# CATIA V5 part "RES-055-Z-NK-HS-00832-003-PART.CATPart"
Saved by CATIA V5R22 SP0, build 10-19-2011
Part number: DISTANZPLATTE_003
Revision: 1
Definition: RES-055-Z-NK-HS-00832-003-PART
Nomenclature: RES-055-Z-NK-HS-00832-003-PART
Property "Pos.:": "003"
Property "Benennung:": "DISTANZPLATTE"
Property "Kom_Nr.:": "15030"
Property "Werkstoff": "1.2343"
Property "Warmbehandlung": "gasnitriert, 38-40HRc EHT 0,012"
Property "Drahtschnitt": "-"
Property "Rundes_Teil": "-"
Property "Fm_laenge": "N.A"
Property "Fm_breite": "N.A"
Property "Fm_hoehe": "N.A"
Property "Rm_laenge": "N.A"
Property "Rm_breite": "N.A"
Property "Rm_hoehe": "N.A"
Property "Fertiggewicht": 0 (mass)
Property "Rohteilgewicht": 0 (mass)
Property "Teiletyp": "--"
Property "DichteMaterial": 0 (density)
Bounding box of the stored display mesh (mm): x -526 to 650, y -400 to 418, z 98 to 158
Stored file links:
  C:\Users\gerco\Desktop\Heck a Becker\HS-832_6_11_2017\OBERTEIL\RES-055-Z-NK-HS-00832-003-PART.CATPart
  X:\Projekte\Ford\045-Z-NK-HS-00270\Stammdaten__\Gueltige-Daten\DGF\AS\Einsatz_AS\RES-045-Z-NK-HS-00270-0085-PRODUCT.CATProduct
  C:\Users\gerco\Desktop\Heck a Becker\HS-832_6_11_2017\RES-055-Z-NK-HS-00832-0001-MP.CATProduct
  C:\Users\gerco\Desktop\Heck a Becker\HS-832_6_11_2017\OBERTEIL\RES-055-Z-NK-HS-00832-002-PART.CATPart
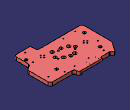
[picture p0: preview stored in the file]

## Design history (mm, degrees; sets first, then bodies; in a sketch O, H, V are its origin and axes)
External parameters (linked from other documents)
  `External.Part-Aktualisiert` = "Nein"
AxisSystem1 "Zeichnung": origin (-88.3577, -2.1174, 100), X (1, 0, 0), Y (0, 1, 0), Z (0, 0, 1)
Set1
  Point1: type Center, Curve DatumCurve1
  DatumCurve1
  Point2: type Center, Curve DatumCurve2
  DatumCurve2
  Sketch1 on start face of Pad1, origin (0, 0, 98), H (1, 0, 0), V (0, -1, 0)
    line L1 (-323.4192, -216.5405) -> (-223.2604, -148.9825)
    reference intersected line E1 through (-172.4335, -116.3079) direction (0.5592, -0.829) from face of DatumSurface1
    perpendicularity: E1 L1
  DatumSurface1
  Sketch2 on start face of Pad1, origin (0, 0, 98), H (1, 0, 0), V (0, -1, 0)
    line L1 (-288.8097, 97.9157) -> (-364.2918, 74.8385)
    reference projected line E1 (-162.6193, 115.1729) -> (-138.8677, 122.4345) from edge of DatumCurve3
    parallelism: L1 E1
  DatumCurve3
  Extract1: ExtractElem face of DatumSurface2
  DatumSurface2
  DatumCurve4
  DatumCurve5
  DatumPoint1
  Sketch3, origin (13, -18, 158), H (1, 0, 0), V (0, 1, 0)
    point P1 (251.3624, -208.4253)
    point P2 (472.1176, -115.8126)
    point P3 (556.6916, 242.4095)
    point P4 (336.7469, 310.6472)
    point P5 (162.6938, 310.4125)
    point P6 (-82.7818, 310.5732)
    point P7 (-333.9619, 325.7225)
    point P8 (-155.8091, -208.4253)
    point P9 (-369.5402, -211.2042)
    point P10 (395.0817, -331.375)
  DatumCurve6
  Sketch4, origin (13, -18, 198), H (1, 0, 0), V (0, -1, 0), geometry linked from another document
  DatumPoint2
  Sketch5, origin (0, 0, 58), H (1, 0, 0), V (0, -1, 0), geometry linked from another document
  DatumPoint3
  Sketch6, origin (0, 0, 58), H (1, 0, 0), V (0, -1, 0), geometry linked from another document
  DatumCurve7 to DatumCurve11
  Sketch7, origin (0, 0, 58), H (1, 0, 0), V (0, -1, 0), geometry linked from another document
  DatumCurve12
  DatumCurve13
  DatumPoint4
  Sketch8, origin (0, 0, 20), H (1, 0, 0), V (0, -1, 0), geometry linked from another document
  DatumCurve14
  DatumCurve15
  Sketch9 on end face of Pad1, origin (0, 0, 158), H (1, 0, 0), V (0, 1, 0)
    point P1 (310, -110)
    point P2 (340, -140)
    point P3 (310, -170)
    point P4 (280, -140)
    reference projected circle E1 centre (280, -140) radius 2.4585 from edge of DatumCurve16
    reference projected circle E2 centre (310, -170) radius 2.4585 from edge of DatumCurve17
    reference projected circle E3 centre (340, -140) radius 2.4585 from edge of DatumCurve18
    reference projected circle E4 centre (310, -110) radius 2.4585 from edge of DatumCurve19
    point P5 (-290.0001, 49.9999)
    point P6 (-260.0001, 19.9999)
    point P7 (-290.0001, -10.0001)
    point P8 (-320.0001, 19.9999)
    reference projected circle E5 centre (-320.0001, 19.9999) radius 2.4585 from edge of DatumCurve20
    reference projected circle E6 centre (-290.0001, 49.9999) radius 5.5 from edge of DatumCurve21
    reference projected circle E7 centre (-260.0001, 19.9999) radius 5.5 from edge of DatumCurve22
    reference projected point E8 (-290.0001, -10.0001) from vertex of DatumPoint5
    concentricity: P4 E1, P3 E2, P2 E3, P1 E4, P8 E5, P5 E6, P6 E7
    coincidence: P7 E8
  DatumCurve16 to DatumCurve22
  DatumPoint5
  Sketch10 on start face of Pad1, origin (0, 0, 98), H (1, 0, 0), V (0, -1, 0)
    point P1 (241.3317, -171.4183)
    point P2 (296.3157, -170.0917)
    point P3 (297.5217, -220.0772)
    point P4 (242.5377, -221.4037)
    reference projected circle E1 centre (241.3317, -171.4183) radius 6.5 from edge of DatumCurve23
    reference projected circle E2 centre (296.3157, -170.0917) radius 6.5 from edge of DatumCurve24
    reference projected circle E3 centre (242.5377, -221.4037) radius 6.5 from edge of DatumCurve25
    reference projected circle E4 centre (297.5217, -220.0772) radius 6.5 from edge of DatumCurve26
    point P5 (303.7518, -318)
    point P6 (504.7518, -318)
    reference projected line E5 (297.2518, -298.6917) -> (297.2518, -333.6917) from edge of DatumCurve29
    reference projected line E6 (498.2518, -298.6917) -> (498.2518, -333.6917) from edge of DatumCurve30
    reference projected line E7 (650, -338) -> (229.3301, -338) from edge [start face of Pad1 | face of Pad1 from Sketch18.L11]
    reference projected line E8 (650, -338) -> (229.3301, -338) from edge [start face of Pad1 | face of Pad1 from Sketch18.L11]
    point P7 (537.8948, 114.8277)
    point P8 (587.104, 80.499)
    point P9 (505.8547, 68.8992)
    point P10 (555.0638, 34.5705)
    reference projected circle E9 centre (587.104, 80.499) radius 6.5 from edge of DatumCurve51
    reference projected circle E10 centre (537.8948, 114.8277) radius 6.5 from edge of DatumCurve52
    reference projected circle E11 centre (555.0638, 34.5705) radius 6.5 from edge of DatumCurve53
    reference projected circle E12 centre (505.8547, 68.8992) radius 6.5 from edge of DatumCurve54
    distance P5 E5 = 6.5
    distance P6 E6 = 6.5
    distance E7 P6 = 20
    distance E8 P5 = 20
    concentricity: P1 E1, P2 E2, P4 E3, P3 E4, P8 E9, P7 E10, P10 E11, P9 E12
  DatumCurve23 to DatumCurve30
  Sketch11 on start face of Pad1, origin (0, 0, 98), H (1, 0, 0), V (0, -1, 0)
    point P1 (-294.3836, -261.3208)
    point P2 (-264.7464, -305.2598)
    point P3 (-397.3924, -394.7307)
    point P4 (-427.0296, -350.7917)
    reference projected circle E1 centre (-427.0296, -350.7917) radius 11.4 from edge of DatumCurve31
    reference projected circle E2 centre (-397.3924, -394.7307) radius 11.4 from edge of DatumCurve32
    reference projected circle E3 centre (-294.3836, -261.3208) radius 11.4 from edge of DatumCurve33
    reference projected circle E4 centre (-264.7464, -305.2598) radius 11.4 from edge of DatumCurve34
    point P5 (-303.3006, 105.6705)
    point P6 (-287.8049, 54.9864)
    point P7 (-456.3094, 58.891)
    point P8 (-440.8137, 8.2069)
    reference projected circle E5 centre (-456.3094, 58.891) radius 11.4 from edge of DatumCurve35
    reference projected circle E6 centre (-440.8137, 8.2069) radius 11.4 from edge of DatumCurve36
    reference projected circle E7 centre (-303.3006, 105.6705) radius 11.4 from edge of DatumCurve37
    reference projected circle E8 centre (-287.8049, 54.9864) radius 11.4 from edge of DatumCurve38
    point P9 (315, 386.5)
    point P10 (315, 333.5)
    point P11 (475, 386.5)
    point P12 (475, 333.5)
    reference projected circle E9 centre (315, 386.5) radius 11.4 from edge of DatumCurve39
    reference projected circle E10 centre (315, 333.5) radius 11.4 from edge of DatumCurve40
    reference projected circle E11 centre (475, 386.5) radius 11.4 from edge of DatumCurve41
    reference projected circle E12 centre (475, 333.5) radius 11.4 from edge of DatumCurve42
    concentricity: P4 E1, E2 P3, P1 E3, P2 E4, P7 E5, P8 E6, P5 E7, P6 E8, P9 E9, P10 E10, P11 E11, P12 E12
  DatumCurve31 to DatumCurve46
  Sketch12 on end face of Pocket1, origin (0, 0, 118), H (1, 0, 0), V (0, -1, 0)
    point P1 (7.4997, -339.4905)
    point P2 (5.65, -392.4582)
    point P3 (-154.2525, -386.8743)
    point P4 (-152.4028, -333.9066)
    reference projected circle E1 centre (-152.4028, -333.9066) radius 11.4 from edge of DatumCurve47
    reference projected circle E2 centre (-154.2525, -386.8743) radius 11.4 from edge of DatumCurve48
    reference projected circle E3 centre (7.4997, -339.4905) radius 11.4 from edge of DatumCurve49
    reference projected circle E4 centre (5.65, -392.4582) radius 11.4 from edge of DatumCurve50
    concentricity: P4 E1, E2 P3, P1 E3, P2 E4
  DatumCurve47 to DatumCurve54
  Sketch13 on start face of Pad1, origin (0, 0, 98), H (1, 0, 0), V (0, -1, 0)
    point P1 (-279.565, -283.2903)
    point P2 (-412.211, -372.7612)
    reference projected circle E1 centre (-412.211, -372.7612) radius 5.5 from edge of DatumCurve55
    reference projected circle E2 centre (-279.565, -283.2903) radius 5.5 from edge of DatumCurve56
    point P3 (-295.5528, 80.3284)
    point P4 (-448.5616, 33.549)
    reference projected circle E3 centre (-448.5616, 33.549) radius 5.5 from edge of DatumCurve57
    reference projected circle E4 centre (-295.5528, 80.3284) radius 5.5 from edge of DatumCurve58
    point P5 (475, 360)
    point P6 (315, 360)
    reference projected circle E5 centre (315, 360) radius 5.5 from edge of DatumCurve59
    reference projected circle E6 centre (475, 360) radius 5.5 from edge of DatumCurve60
    point P7 (562.4994, 97.6633)
    point P8 (530.4592, 51.7348)
    reference projected circle E7 centre (530.4592, 51.7348) radius 5.5 from edge of DatumCurve61
    reference projected circle E8 centre (562.4994, 97.6633) radius 5.5 from edge of DatumCurve62
    point P9 (276.3216, -170.5741)
    point P10 (262.5319, -220.9213)
    reference projected circle E9 centre (276.3216, -170.5741) radius 5 from edge of DatumCurve96
    reference projected circle E10 centre (262.5319, -220.9213) radius 5 from edge of DatumCurve97
    concentricity: P2 E1, P1 E2, E3 P4, P3 E4, P6 E5, P5 E6, P8 E7, P7 E8, P9 E9, P10 E10
  DatumCurve55 to DatumCurve62
  Sketch14 on start face of Pad1, origin (0, 0, 98), H (1, 0, 0), V (0, -1, 0)
    point P1 (-402.6103, -199.2242)
    point P2 (-430.5699, -157.7723)
    point P3 (-513.4737, -213.6916)
    point P4 (-485.5141, -255.1435)
    reference projected circle E1 centre (-485.5141, -255.1435) radius 4.4 from edge of DatumCurve63
    reference projected circle E2 centre (-513.4737, -213.6916) radius 4.4 from edge of DatumCurve64
    reference projected circle E3 centre (-402.6103, -199.2242) radius 4.4 from edge of DatumCurve65
    reference projected circle E4 centre (-430.5699, -157.7723) radius 4.4 from edge of DatumCurve66
    point P5 (-403.2616, 244.5115)
    point P6 (-498.8921, 215.2743)
    point P7 (-484.2735, 167.459)
    point P8 (-388.643, 196.6962)
    reference projected circle E5 centre (-388.643, 196.6962) radius 4.4 from edge of DatumCurve67
    reference projected circle E6 centre (-403.2616, 244.5115) radius 4.4 from edge of DatumCurve68
    reference projected circle E7 centre (-498.8921, 215.2743) radius 5.5 from edge of DatumCurve69
    reference projected circle E8 centre (-484.2735, 167.459) radius 4.4 from edge of DatumCurve70
    point P9 (470, 221.5)
    point P10 (370, 221.5)
    point P11 (370, 171.5)
    point P12 (470, 171.5)
    reference projected circle E9 centre (370, 221.5) radius 4.4 from edge of DatumCurve71
    reference projected circle E10 centre (470, 221.5) radius 5.5 from edge of DatumCurve72
    reference projected arc E11 centre (470, 171.5) radius 2.86 from (472.453, 172.9705) to (470.047, 174.3596) ccw from edge of DatumCurve73
    reference projected circle E12 centre (370, 171.5) radius 5.5 from edge of DatumCurve74
    point P13 (556.1354, -46.0403)
    point P14 (527.5281, -87.0479)
    point P15 (609.5433, -144.2625)
    point P16 (638.1506, -103.2549)
    reference projected circle E13 centre (638.1506, -103.2549) radius 5.5 from edge of DatumCurve75
    reference projected circle E14 centre (609.5433, -144.2625) radius 5.5 from edge of DatumCurve76
    reference projected circle E15 centre (556.1354, -46.0403) radius 5.5 from edge of DatumCurve77
    reference projected circle E16 centre (527.5281, -87.0479) radius 5.5 from edge of DatumCurve78
    concentricity: P4 E1, P3 E2, P1 E3, P2 E4, E5 P8, P5 E6, P6 E7, P7 E8, P10 E9, P9 E10, P12 E11, P11 E12, P16 E13, P15 E14, P13 E15, P14 E16
  DatumCurve63 to DatumCurve82
  Sketch15 on start face of Pad1, origin (0, 0, 98), H (1, 0, 0), V (0, -1, 0)
    point P1 (-493.3428, -243.537)
    point P2 (-410.439, -187.6177)
    reference projected circle E1 centre (-493.3428, -243.537) radius 3 from edge of DatumCurve83
    reference projected circle E2 centre (-410.439, -187.6177) radius 2.7856 from edge of DatumCurve84
    point P3 (-392.7363, 210.0845)
    point P4 (-488.3667, 180.8473)
    reference projected circle E3 centre (-488.3667, 180.8473) radius 3 from edge of DatumCurve85
    reference projected circle E4 centre (-392.7363, 210.0845) radius 1.65 from edge of DatumCurve86
    point P5 (470, 207.5)
    point P6 (370, 207.5)
    reference projected circle E5 centre (370, 207.5) radius 3 from edge of DatumCurve87
    reference projected circle E6 centre (470, 207.5) radius 2.7856 from edge of DatumCurve88
    point P7 (630.1405, -114.7371)
    point P8 (548.1253, -57.5225)
    reference projected circle E7 centre (548.1253, -57.5225) radius 3 from edge of DatumCurve89
    reference projected circle E8 centre (630.1405, -114.7371) radius 3 from edge of DatumCurve90
    concentricity: E1 P1, P2 E2, P4 E3, P3 E4, P6 E5, P5 E6, P8 E7, E8 P7
  DatumCurve83 to DatumCurve90
  Sketch16 on end face of Pocket1, origin (0, 0, 118), H (1, 0, 0), V (0, -1, 0)
    point P1 (47.4404, -341.8859)
    point P2 (147.3795, -345.3759)
    reference projected circle E1 centre (47.4404, -341.8859) radius 3 from edge of DatumCurve91
    reference projected circle E2 centre (147.3795, -345.3759) radius 3 from edge of DatumCurve92
    concentricity: P1 E1, P2 E2
  DatumCurve91 to DatumCurve93
  DatumSurface3
  DatumCurve94
  DatumSurface4
  DatumCurve95
  DatumSurface5
  DatumCurve96
  DatumCurve97
Set2 "Berechnen"
  Plane1 "Pos-XY": type Offset, RefPlane xy-plane, Offset 0
  Plane2 "Pos-YZ": type Offset, RefPlane yz-plane, Offset 0
  Plane3 "Pos-ZX": type Offset, RefPlane zx-plane, Offset 0
  UdfFeature1 "Fertigmass.A": UdfInputSpec1 Extremum1, UdfInputSpec2 edge [XY plane of AxisSystem1 | ZX plane of AxisSystem1], UdfInputSpec3 edge [YZ plane of AxisSystem1 | XY plane of AxisSystem1], UdfInputSpec4 edge [ZX plane of AxisSystem1 | YZ plane of AxisSystem1], UdfInputSpec5 Extremum2, UdfInputSpec6 edge [XY plane of AxisSystem1 | ZX plane of AxisSystem1], Abmessungen "16mm x 16mm x 615,406mm", X 16, Y 16, Z 615.406, UdfInputSpec7 edge [YZ plane of AxisSystem1 | XY plane of AxisSystem1], UdfInputSpec8 edge [ZX plane of AxisSystem1 | YZ plane of AxisSystem1], UdfInputSpec9 Extremum3, UdfInputSpec10 edge [YZ plane of AxisSystem1 | XY plane of AxisSystem1], UdfInputSpec11 edge [XY plane of AxisSystem1 | ZX plane of AxisSystem1], UdfActivity false, UdfInputSpec12 edge [ZX plane of AxisSystem1 | YZ plane of AxisSystem1], UdfInputSpec13 Extremum4, UdfInputSpec14 edge [YZ plane of AxisSystem1 | XY plane of AxisSystem1], UdfInputSpec15 edge [XY plane of AxisSystem1 | ZX plane of AxisSystem1], UdfInputSpec16 edge [ZX plane of AxisSystem1 | YZ plane of AxisSystem1], UdfInputSpec17 Extremum5, UdfInputSpec18 edge [ZX plane of AxisSystem1 | YZ plane of AxisSystem1], UdfInputSpec19 edge [XY plane of AxisSystem1 | ZX plane of AxisSystem1], UdfInputSpec20 edge [YZ plane of AxisSystem1 | XY plane of AxisSystem1], UdfOutputs Trim3, UdfInputSpec21 Extremum6, UdfInputSpec22 edge [ZX plane of AxisSystem1 | YZ plane of AxisSystem1], UdfActivityImpacts (edge [XY plane of AxisSystem1 | ZX plane of AxisSystem1]; edge [YZ plane of AxisSystem1 | XY plane of AxisSystem1]; Plane6; Plane7; Plane8; Plane9; Plane10; Plane11; Intersect1; Intersect2; Intersect3; Intersect4; Intersect5; Intersect6; Intersect7; Intersect8; Intersect9; Intersect10; Intersect11; Intersect12; Trim1; Trim2; Trim4; Trim5; Trim6; Split1; Split2; Split3; Split4; Point3; Plane12; Plane13; Plane14; Plane15; Plane16; Plane17), UdfInputSpec25 {planeoffsetpt RefPlane YZ plane of AxisSystem1, RefPoint Extremum1}, UdfInputSpec26 {planeoffsetpt RefPlane YZ plane of AxisSystem1, RefPoint Extremum2}, UdfInputSpec27 {planeoffsetpt RefPlane ZX plane of AxisSystem1, RefPoint Extremum3}, UdfInputSpec28 {planeoffsetpt RefPlane ZX plane of AxisSystem1, RefPoint Extremum4}, UdfInputSpec29 {planeoffsetpt RefPlane XY plane of AxisSystem1, RefPoint Extremum5}, UdfInputSpec30 {planeoffsetpt RefPlane XY plane of AxisSystem1, RefPoint Extremum6}
  DatumSurface6
  Plane4 "Pos-YZ": stored without definition
  Plane5 "Pos-ZX": stored without definition
  Sketch17 on end face of Pocket1, origin (0, 0, 118), H (1, 0, 0), V (0, -1, 0)
    point P1 (6.5749, -365.9744)
    point P2 (-153.3277, -360.3905)
    reference projected circle E1 centre (-153.3277, -360.3905) radius 5.5 from edge of DatumCurve98
    reference projected circle E2 centre (6.5749, -365.9744) radius 5.5 from edge of DatumCurve99
    concentricity: P2 E1, P1 E2
  DatumCurve98
  DatumCurve99
Body1 (main body)
  Body2 "Grundkörper"
    Body3
      Sketch18 on face of DatumSurface6, origin (0, 0, 98), H (1, 0, 0), V (0, 1, 0)
        line L1 (-411, 418) -> (-404.0042, 418)
        line L2 (550, -400) -> (264, -400)
        line L3 (-526, -280) -> (-526, 247.5055)
        point P1 (550, 400)
        reference intersected line E1 through (0, 0) direction (0, 1) from Plane4
        reference intersected line E2 through (0, 0) direction (-1, 0) from Plane5
        line L4 (550, -128.4331) -> (650, -58.6722)
        reference projected line E3 (622.675, -70.3157) -> (536.5591, -130.391) from edge of DatumCurve4
        line L5 (550, -128.4331) -> (550, -400)
        point P4 (550, 230)
        reference intersected line E4 through (0, 0) direction (-1, 0) from zx-plane
        line L6 (-411, 418) -> (-526, 247.5055)
        point P6 (-411, 418)
        reference projected line E5 (-406.4241, 417.1065) -> (-451.1595, 350.7835) from edge of DatumCurve5
        line L7 (650, 338) -> (650, -58.6722)
        line L8 (264, -400) -> (264, -280)
        point P10 (264, -280)
        line L9 (264, -280) -> (-526, -280)
        point P11 (-336, -280)
        line L10 (229.3301, 418) -> (229.3301, 338)
        line L11 (229.3301, 338) -> (650, 338)
        line L12 (-346, 383) -> (-206, 383)
        line L13 (-186, 403) -> (-186, 418)
        line L14 (-186, 418) -> (229.3301, 418)
        arc A1 centre (-346, 403) radius 20 from (-346, 383) to (-357.1839, 386.4192) cw
        arc A2 centre (-206, 403) radius 20 from (-206, 383) to (-186, 403) ccw
        line L15 (-357.1839, 386.4192) -> (-404.0042, 418)
        distance E1 L3 = 526
        distance E2 L1 = 418
        distance P4 L2 = 630
        distance E4 L2 = 400
        distance L3 P6 = 115
        distance L5 L7 = 100
        distance L5 L3 = 1076
        distance L9 L2 = 120
        distance P10 P11 = 600
        distance L1 L11 = 80
        distance L12 L1 = 35
        radius A1 = 20
        radius A2 = 20
        horizontal: L1 H, L2 H, L9 H, L11 H, L12 H
        vertical: L3 V, L7 V, L8 V, L10 V, L13 V
        parallelism: E3 L4, L6 E5
        coincidence: P6 L1, P11 L9, L1 L14
        tangency: A1 L12, A2 L12, A2 L13, L15 A1
        perpendicularity: L15 L6
      Pad1: profile Sketch18, direction (0, 0, 1), length 60
    Assemble1: tool Body3
    Fillet1: radius 40, on edge [face of Pad1 from Sketch18.L5 | face of Pad1 from Sketch18.L2]; edge [face of Pad1 from Sketch18.L4 | face of Pad1 from Sketch18.L5] (x2); edge [face of Pad1 from Sketch18.L3 | face of Pad1 from Sketch18.L6]; edge [face of Pad1 from Sketch18.L7 | face of Pad1 from Sketch18.L4]; edge [face of Pad1 from Sketch18.L8 | face of Pad1 from Sketch18.L9]; edge [face of Pad1 from Sketch18.L9 | face of Pad1 from Sketch18.L3]; edge [face of Pad1 from Sketch18.L11 | face of Pad1 from Sketch18.L7]; edge [face of Pad1 from Sketch18.L10 | face of Pad1 from Sketch18.L11]; edge [face of Pad1 from Sketch18.L14 | face of Pad1 from Sketch18.L10]
  Assemble2 "Grundkörper": tool Body2
  Body4 "Fräsbearbeitung"
    Body5
      Sketch19 on start face of Pad1, origin (0, 0, 98), H (1, 0, 0), V (0, -1, 0)
        line L1 (-191, -427.6592) -> (161, -427.6592)
        line L2 (161, -427.6592) -> (161, -327)
        line L3 (150, -316) -> (-180, -316)
        line L4 (-191, -327) -> (-191, -427.6592)
        point P3 (161, -316)
        point P4 (-191, -316)
        reference projected line E1 (-526, -247.5055) -> (-526, 280) from edge [start face of Pad1 | face of Pad1 from Sketch18.L3]
        arc A1 centre (-180, -327) radius 11 from (-191, -327) to (-180, -316) cw
        arc A2 centre (150, -327) radius 11 from (150, -316) to (161, -327) cw
        reference projected line E2 (-404.0042, -418) -> (-411, -418) from edge [start face of Pad1 | face of Pad1 from Sketch18.L1]
        distance L4 E1 = 335
        distance P3 P4 = 352
        radius A1 = 11
        radius A2 = 11
        distance L3 E2 = 102
        horizontal: L1 H, L3 H
        vertical: L2 V, L4 V
        coincidence: L4 P4, L3 P4, L3 P3, L2 P3
        tangency: A1 L4, A1 L3, A2 L3, A2 L2
      Pocket1: profile Sketch19, direction (0, 0, 1), length 20
    Assemble3: tool Body5
    Body6
      Sketch20 on end face of Pad1, origin (-420, -131, 158), H (1, 0, 0), V (0, 1, 0)
        point P1 (0, 0)
        reference projected point E1 (0, 0) from vertex of Sketch4
        coincidence: E1 P1
      Hole1: placed by Sketch20, at (-420, -131, 158) direction (0, 0, -1), diameter 50, depth 5
      UserPattern1: of the body so far, copies 4, at the points of Sketch4
    Assemble4: tool Body6
    Body7
      Sketch21 on start face of Pad1, origin (-130, 0, 98), H (1, 0, 0), V (0, -1, 0)
        point P1 (0, 0)
        reference projected point E1 (0, 0) from vertex of DatumPoint2
        coincidence: E1 P1
      Hole2: placed by Sketch21, at (-130, 0, 98) direction (0, 0, 1), diameter 55, depth 70
      UserPattern2: of the body so far, copies 4, at the points of Sketch5
    Assemble5: tool Body7
    Body8
      Sketch22 on start face of Pad1, origin (-75, -63, 98), H (1, 0, 0), V (0, -1, 0)
        point P1 (0, 0)
        reference projected point E1 (0, 0) from vertex of DatumPoint3
        coincidence: E1 P1
      Hole3: placed by Sketch22, at (-75, -63, 98) direction (0, 0, 1), diameter 62, depth 70
      UserPattern3: of the body so far, copies 4, at the points of Sketch7
    Assemble6: tool Body8
    Body9
      Sketch23 on start face of Pad1, origin (391.3896, -114.9501, 98), H (1, 0, 0), V (0, -1, 0)
        point P1 (-81.3896, 25.0499)
        reference projected line E1 (258.6104, -56.2779) -> (258.6104, -452.9501) from edge [start face of Pad1 | face of Pad1 from Sketch18.L7]
        distance P1 E1 = 340
      Hole4: placed by Sketch23, at (310, -140, 98) direction (0, 0, 1), diameter 72, depth 5
      Sketch24 on start face of Pad1, origin (-260.8683, 132.2894, 98), H (1, 0, 0), V (0, -1, 0)
        point P1 (-29.1318, 112.2895)
        reference projected circle E1 centre (-29.1318, 112.2895) radius 36.5 from edge of DatumCurve13
        concentricity: E1 P1
      Hole5: placed by Sketch24, at (-290.0001, 19.9999, 98) direction (0, 0, 1), diameter 72, depth 5
    Assemble7: tool Body9
  Assemble8 "Fräsbearbeitung": tool Body4
  Body10 "Bohrbearbeitung"
    Body11
      Sketch25 on start face of Pad1, origin (-142.8091, -226.4253, 98), H (1, 0, 0), V (0, -1, 0)
        point P1 (0, 0)
        reference projected point E1 (0, 0) from vertex of DatumPoint1
        coincidence: E1 P1
      Hole6: placed by Sketch25, at (-142.8091, -226.4253, 98) direction (0, 0, 1), diameter 17.5, depth 70, V-bottom angle 120, counterbore diameter 26, counterbore depth 20
      UserPattern4: of the body so far, copies 10, at the points of Sketch3
      Sketch26 on start face of Pad1, origin (-413.7417, 88.9584, 98), H (1, 0, 0), V (0, -1, 0)
        point P1 (-1.0954, -22.1361)
        reference projected circle E1 centre (-1.0954, -22.1361) radius 13 from edge of DatumCurve6
        concentricity: E1 P1
      Hole7: placed by Sketch26, at (-414.8371, 111.0945, 98) direction (0, 0, 1), diameter 17.5, depth 70, V-bottom angle 120, counterbore diameter 26, counterbore depth 20
    Assemble9: tool Body11
    Body12
      Sketch27 on start face of Pad1, origin (510, -230, 98), H (1, 0, 0), V (0, -1, 0)
        point P1 (0, 0)
        reference projected point E1 (0, 0) from vertex of Sketch4
        coincidence: E1 P1
      Hole8: placed by Sketch27, at (510, -230, 98) direction (0, 0, 1), diameter 17.5, depth 70, counterbore diameter 26, counterbore depth 20
      UserPattern5: of the body so far, copies 4, at the points of Sketch4
    Assemble10: tool Body12
    Body13
    Assemble11: tool Body13
    Body14
      Sketch28 on end face of Pad1, origin (92.5241, -72.237, 158), H (1, 0, 0), V (0, 1, 0)
        point P1 (-7.5241, -12.763)
        reference projected arc E1 centre (-7.5241, -12.763) radius 12.15 from (-7.5241, -24.913) to (-7.5241, -0.613) ccw from edge of DatumCurve8
        concentricity: E1 P1
      Hole9: placed by Sketch28, at (85, -85, 158) direction (0, 0, -1), diameter 26, depth 70
      Sketch29 on end face of Pad1, origin (-90.6179, 57.2443, 158), H (1, 0, 0), V (0, 1, 0)
        point P1 (-1.3821, -22.2443)
        reference projected arc E1 centre (-1.3821, -22.2443) radius 12.15 from (-1.3821, -34.3943) to (-1.3821, -10.0943) ccw from edge of DatumCurve10
        concentricity: P1 E1
      Hole10: placed by Sketch29, at (-92, 35, 158) direction (0, 0, -1), diameter 26, depth 70
      Sketch30 on end face of Pad1, origin (207.5247, 56.9941, 158), H (1, 0, 0), V (0, 1, 0)
        point P1 (2.4753, -21.9941)
        reference projected arc E1 centre (2.4753, -21.9941) radius 12.15 from (2.4753, -34.1441) to (2.4753, -9.8441) ccw from edge of DatumCurve11
        concentricity: E1 P1
      Hole11: placed by Sketch30, at (210, 35, 158) direction (0, 0, -1), diameter 26, depth 70
    Assemble12: tool Body14
    Body15
      Sketch31 on start face of Pad1, origin (290, 14, 98), H (1, 0, 0), V (0, -1, 0)
        point P1 (0, 0)
        reference projected point E1 (0, 0) from vertex of DatumPoint4
        coincidence: E1 P1
      Hole12: placed by Sketch31, at (290, 14, 98) direction (0, 0, 1), diameter 10, depth 30, V-bottom angle 120, threaded "M12", thread diameter 12, thread depth 25, pitch 1
      UserPattern6: of the body so far, copies 4, at the points of Sketch8
    Assemble13: tool Body15
    Body16
      Sketch32 on start face of Pad1, origin (270.5618, 53.2459, 98), H (1, 0, 0), V (0, -1, 0)
        point P1 (0.4382, 3.2459)
        reference projected circle E1 centre (0.4382, 3.2459) radius 6 from edge of DatumCurve14
        concentricity: E1 P1
      Hole13: placed by Sketch32, at (271, 50, 98) direction (0, 0, 1), diameter 12, depth 20, V-bottom angle 120
      Sketch33 on start face of Pad1, origin (-200.8605, -79.1616, 98), H (1, 0, 0), V (0, -1, 0)
        point P1 (0.8605, 0.8384)
        reference projected circle E1 centre (0.8605, 0.8384) radius 6 from edge of DatumCurve15
        concentricity: E1 P1
      Hole14: placed by Sketch33, at (-200, -80, 98) direction (0, 0, 1), diameter 12, depth 20, V-bottom angle 120
    Assemble14: tool Body16
    Body17
      Sketch34 on end face of Pad1, origin (-320.0001, 19.9999, 158), H (1, 0, 0), V (0, 1, 0)
        point P1 (0, 0)
        reference projected point E1 (0, 0) from Sketch9.P8
        coincidence: E1 P1
      Hole15: placed by Sketch34, at (-320.0001, 19.9999, 158) direction (0, 0, -1), diameter 11, depth 60, V-bottom angle 120, counterbore diameter 18, counterbore depth 20
      UserPattern7: of the body so far, copies 8, at the points of Sketch9
    Assemble15: tool Body17
    Body18
      Sketch35 on start face of Pad1, origin (241.3317, 171.4183, 98), H (1, 0, 0), V (0, -1, 0)
        point P1 (0, 0)
        reference projected point E1 (0, 0) from Sketch10.P1
        coincidence: E1 P1
      Hole16: placed by Sketch35, at (241.3317, 171.4183, 98) direction (0, 0, 1), diameter 10, depth 30, V-bottom angle 120, threaded "M12", thread diameter 12, thread depth 25, pitch 1
      UserPattern8: of the body so far, copies 10, at the points of Sketch10
    Assemble16: tool Body18
    Body19
      Sketch36 on start face of Pad1, origin (-456.3094, -58.891, 98), H (1, 0, 0), V (0, -1, 0)
        point P1 (0, 0)
        reference projected point E1 (0, 0) from Sketch11.P7
        coincidence: E1 P1
      Hole17: placed by Sketch36, at (-456.3094, -58.891, 98) direction (0, 0, 1), diameter 13, depth 35, V-bottom angle 120, threaded "M16", thread diameter 16, thread depth 30, pitch 2
      UserPattern9: of the body so far, copies 12, at the points of Sketch11
      Sketch37 on end face of Pocket1, origin (-154.2525, 386.8743, 118), H (1, 0, 0), V (0, 1, 0)
        point P1 (0, 0)
        reference projected point E1 (0, 0) from Sketch12.P3
        coincidence: E1 P1
      Hole18: placed by Sketch37, at (-154.2525, 386.8743, 118) direction (0, 0, 1), diameter 13, depth 35, V-bottom angle 120, threaded "M16", thread diameter 16, thread depth 30, pitch 2
      UserPattern10: of Hole18, copies 4, at the points of Sketch12
    Assemble17: tool Body19
    Body20
      Sketch38 on start face of Pad1, origin (-448.5616, -33.549, 98), H (1, 0, 0), V (0, -1, 0)
        point P1 (0, 0)
        reference projected point E1 (0, 0) from Sketch13.P4
        coincidence: E1 P1
      Hole19: placed by Sketch38, at (-448.5616, -33.549, 98) direction (0, 0, 1), diameter 10, depth 20, V-bottom angle 120
      UserPattern11: of the body so far, copies 10, at the points of Sketch13
      Sketch39 on end face of Pocket1, origin (6.5749, 365.9744, 118), H (1, 0, 0), V (0, 1, 0)
        point P1 (0, 0)
        reference projected point E1 (0, 0) from Sketch17.P1
        coincidence: E1 P1
      Hole20: placed by Sketch39, at (6.5749, 365.9744, 118) direction (0, 0, 1), diameter 10, depth 20, V-bottom angle 120
      UserPattern12: of Hole20, copies 2, at the points of Sketch17
    Assemble18: tool Body20
    Body21
      Sketch40 on start face of Pad1, origin (-513.4737, 213.6916, 98), H (1, 0, 0), V (0, -1, 0)
        point P1 (0, 0)
        reference projected point E1 (0, 0) from Sketch14.P3
        coincidence: E1 P1
      Hole21: placed by Sketch40, at (-513.4737, 213.6916, 98) direction (0, 0, 1), diameter 4.917, depth 17, V-bottom angle 120, threaded, thread diameter 6, thread depth 12, pitch 1
      UserPattern13: of the body so far, copies 16, at the points of Sketch14
      Sketch41 on end face of Pocket1, origin (146.1231, 381.3539, 118), H (1, 0, 0), V (0, 1, 0)
        point P1 (0, 0)
        reference projected point E1 (0, 0) from Sketch42.P4
        coincidence: E1 P1
      Hole22: placed by Sketch41, at (146.1231, 381.3539, 118) direction (0, 0, 1), diameter 4.917, depth 17, V-bottom angle 120, threaded, thread diameter 6, thread depth 12, pitch 1
      Sketch42 on end face of Pocket1, origin (0, 0, 118), H (1, 0, 0), V (0, -1, 0)
        point P1 (47.929, -327.8944)
        point P2 (46.184, -377.864)
        point P3 (147.8681, -331.3844)
        point P4 (146.1231, -381.3539)
        reference projected circle E1 centre (146.1231, -381.3539) radius 3.3 from edge of DatumCurve79
        reference projected circle E2 centre (147.8681, -331.3844) radius 3.3 from edge of DatumCurve80
        reference projected circle E3 centre (47.929, -327.8944) radius 3.3 from edge of DatumCurve81
        reference projected circle E4 centre (46.184, -377.864) radius 5.5 from edge of DatumCurve82
        concentricity: E1 P4, P3 E2, P1 E3, P2 E4
      UserPattern14: of Hole22, copies 4, at the points of Sketch42
    Assemble19: tool Body21
    Body22
      Sketch43 on start face of Pad1, origin (630.1405, 114.7371, 98), H (1, 0, 0), V (0, -1, 0)
        point P1 (0, 0)
        reference projected point E1 (0, 0) from Sketch15.P7
        coincidence: E1 P1
      Hole23: placed by Sketch43, at (630.1405, 114.7371, 98) direction (0, 0, 1), diameter 6, depth 15, V-bottom angle 120
      UserPattern15: of the body so far, copies 8, at the points of Sketch15
      Sketch44 on end face of Pocket1, origin (47.4404, 341.8859, 118), H (1, 0, 0), V (0, 1, 0)
        point P1 (0, 0)
        reference projected point E1 (0, 0) from Sketch16.P1
        coincidence: E1 P1
      Hole24: placed by Sketch44, at (47.4404, 341.8859, 118) direction (0, 0, 1), diameter 6, depth 15, V-bottom angle 120
      UserPattern16: of Hole24, copies 2, at the points of Sketch16
    Assemble20: tool Body22
  Assemble21 "Bohrbearbeitung": tool Body10
Set3 "Geo_Rohteil"
  Extremum1: Reference Body1, Direction edge [XY plane of AxisSystem1 | ZX plane of AxisSystem1], Direction2 edge [YZ plane of AxisSystem1 | XY plane of AxisSystem1], Direction3 edge [ZX plane of AxisSystem1 | YZ plane of AxisSystem1]
  Extremum2: Reference Body1, Direction edge [XY plane of AxisSystem1 | ZX plane of AxisSystem1], Direction2 edge [YZ plane of AxisSystem1 | XY plane of AxisSystem1], Direction3 edge [ZX plane of AxisSystem1 | YZ plane of AxisSystem1]
  Extremum3: Reference Body1, Direction edge [YZ plane of AxisSystem1 | XY plane of AxisSystem1], Direction2 edge [XY plane of AxisSystem1 | ZX plane of AxisSystem1], Direction3 edge [ZX plane of AxisSystem1 | YZ plane of AxisSystem1]
  Extremum4: Reference Body1, Direction edge [YZ plane of AxisSystem1 | XY plane of AxisSystem1], Direction2 edge [XY plane of AxisSystem1 | ZX plane of AxisSystem1], Direction3 edge [ZX plane of AxisSystem1 | YZ plane of AxisSystem1]
  Extremum5: Reference Body1, Direction edge [ZX plane of AxisSystem1 | YZ plane of AxisSystem1], Direction2 edge [XY plane of AxisSystem1 | ZX plane of AxisSystem1], Direction3 edge [YZ plane of AxisSystem1 | XY plane of AxisSystem1]
  Extremum6: Reference Body1, Direction edge [ZX plane of AxisSystem1 | YZ plane of AxisSystem1], Direction2 edge [XY plane of AxisSystem1 | ZX plane of AxisSystem1], Direction3 edge [YZ plane of AxisSystem1 | XY plane of AxisSystem1]
  Plane6: type OffsetPt, RefPlane YZ plane of AxisSystem1, RefPoint Extremum1
  Plane7: type OffsetPt, RefPlane YZ plane of AxisSystem1, RefPoint Extremum2
  Plane8: type OffsetPt, RefPlane ZX plane of AxisSystem1, RefPoint Extremum3
  Plane9: type OffsetPt, RefPlane ZX plane of AxisSystem1, RefPoint Extremum4
  Plane10: type OffsetPt, RefPlane XY plane of AxisSystem1, RefPoint Extremum5
  Plane11: type OffsetPt, RefPlane XY plane of AxisSystem1, RefPoint Extremum6
  Intersect1: ToIntersect1 Plane15, ToIntersect2 Plane12
  Intersect2: ToIntersect1 Plane15, ToIntersect2 Plane13
  Intersect3: ToIntersect1 Plane12, ToIntersect2 Plane14
  Intersect4: ToIntersect1 Plane13, ToIntersect2 Plane14
  Intersect5: ToIntersect1 Plane15, ToIntersect2 Plane17
  Intersect6: ToIntersect1 Plane14, ToIntersect2 Plane17
  Intersect7: ToIntersect1 Plane15, ToIntersect2 Plane16
  Intersect8: ToIntersect1 Plane14, ToIntersect2 Plane16
  Intersect9: ToIntersect1 Plane13, ToIntersect2 Plane17
  Intersect10: ToIntersect1 Plane12, ToIntersect2 Plane17
  Intersect11: ToIntersect1 Plane12, ToIntersect2 Plane16
  Intersect12: ToIntersect1 Plane13, ToIntersect2 Plane16
  Trim1: Element1 Intersect1, Element2 Intersect5
  Trim2: Element1 Intersect2, Element2 Trim1
  Trim3: Element1 Trim2, Element2 Intersect7
  Trim4: Element1 Intersect3, Element2 Intersect6
  Trim5: Element1 Trim4, Element2 Intersect4
  Trim6: Element1 Trim5, Element2 Intersect8
  Split1: ToCut Intersect10, Cutting (Plane15; Plane14)
  Split2: ToCut Intersect9, Cutting (Plane15; Plane14)
  Split3: ToCut Intersect11, Cutting (Plane15; Plane14)
  Split4: ToCut Intersect12, Cutting (Plane15; Plane14)
  Point3: (20, 30, 40)
  Plane12: type Offset, RefPlane Plane6, Offset 0
  Plane13: type Offset, RefPlane Plane7, Offset 0
  Plane14: type Offset, RefPlane Plane8, Offset 0
  Plane15: type Offset, RefPlane Plane9, Offset 0
  Plane16: type Offset, RefPlane Plane10, Offset 0
  Plane17: type Offset, RefPlane Plane11, Offset 0
Relations
  rule "Aktuell":
    /*Regel erzeugt von: achenbach 05.09.2008*/
    if `External.Part-Aktualisiert` == "Ja"
    {
    	Activity = false
    	UdfFeature1.Activity= true
    	Activity = true
    	`gelöscht_Boolean` = true
    	`gelöscht_Boolean`   = true
    }
    if `External.Part-Aktualisiert` == "Nein"
    {
    	UdfFeature1.Activity= false
    	`gelöscht_Boolean` = false
    	`gelöscht_Boolean` = false
    	Activity = false
    	Activity = true
    }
